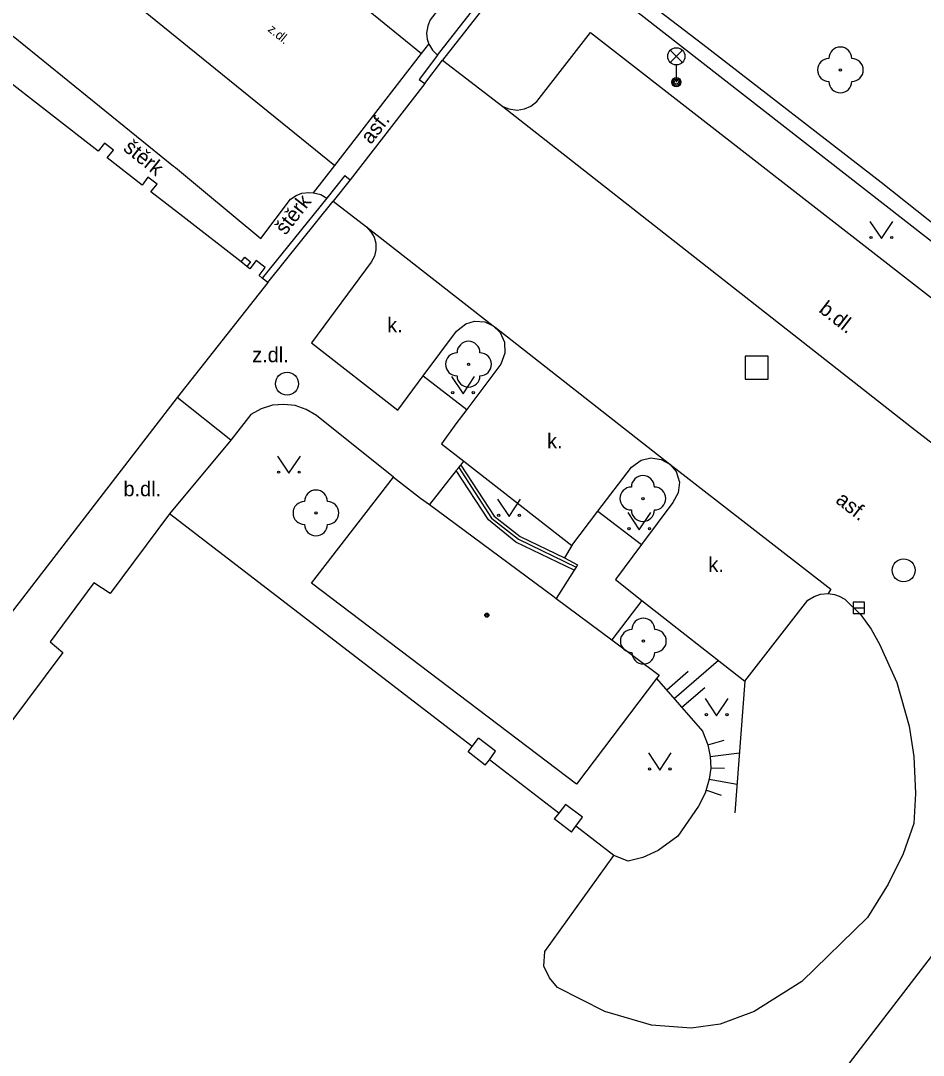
# Model space of a CAD drawing. Extents: x -598932 to -598196, y -1162207 to -1161504.
# Drawn here: x -598730.26 to -598690.86, y -1162044.52 to -1161999.37 of the extents above; entities that cross this region are included whole.
import ezdxf

# ---------------------------------------------------------------- set-up
doc = ezdxf.new("R2010")
doc.units = 0
for name, color, linetype in [('Level 22', 7, 'Continuous'), ('Level 26', 7, 'Continuous'), ('Level 27', 7, 'Continuous'), ('Level 33', 7, 'Continuous'), ('Level 36', 7, 'Continuous'), ('Level 39', 7, 'Continuous'), ('silnoproud - povrch.  znaky a  RIS  skut. velikost', 7, 'Continuous'), ('specificka linie pasportu komunikaci', 7, 'Continuous'), ('TM - budovy zdene_ betonove - VP', 7, 'Continuous'), ('TM - chodniky - VP', 7, 'Continuous'), ('TM - dolni hrana svahu', 7, 'Continuous'), ('TM - horni hrana svahu', 7, 'Continuous'), ('TM - komunikace - VP', 7, 'Continuous'), ('TM - letecke snimky - pomocna linie', 7, 'Continuous'), ('TM - plot zdeny_ ohradni zed - VP', 7, 'Continuous'), ('TM - podezdivka plotu - VP', 7, 'Continuous'), ('TM - popis povrchu', 7, 'Continuous'), ('TM - rozhrani mezi zpev. plochami mezi sebou - VP', 7, 'Continuous'), ('TM - rozhrani ploch obecne - VP', 7, 'Continuous'), ('TM - srafovani', 7, 'Continuous'), ('TM - vjezd na pozemek', 7, 'Continuous'), ('TM - zabradli - VP', 7, 'Continuous')]:
    doc.layers.add(name, color=color, linetype=linetype)

msp = doc.modelspace()

# ---------------------------------------------------------------- linework, layer by layer
at = {"layer": 'Level 22'}
for centre in [(-598694.48, -1162001.52), (-598710.71, -1162014.36), (-598703.1, -1162020.22), (-598717.37, -1162020.85), (-598703.08, -1162026.44)]:
    msp.add_circle(centre, 0.05, dxfattribs=at)
for centre, start, end in [((-598694.48, -1162001.02), 359.9626, 179.9626), ((-598694.98, -1162001.52), 89.9626, 269.9626), ((-598693.98, -1162001.52), 269.9626, 89.9626), ((-598694.48, -1162002.02), 179.9626, 359.9626), ((-598710.71, -1162013.86), 0, 180), ((-598711.21, -1162014.36), 90, 270), ((-598710.21, -1162014.36), 270, 90), ((-598710.71, -1162014.86), 180, 0), ((-598703.1, -1162019.72), 0, 180), ((-598717.37, -1162020.35), 0, 180), ((-598703.6, -1162020.22), 90, 270), ((-598702.6, -1162020.22), 270, 90), ((-598717.87, -1162020.85), 90, 270), ((-598716.87, -1162020.85), 270, 90), ((-598703.1, -1162020.72), 180, 0), ((-598717.37, -1162021.35), 180, 0), ((-598703.08, -1162025.94), 0, 180), ((-598703.58, -1162026.44), 90, 270), ((-598702.58, -1162026.44), 270, 90), ((-598703.08, -1162026.94), 180, 0)]:
    msp.add_arc(centre, 0.5, start, end, dxfattribs=at)
at = {"layer": 'Level 26'}
msp.add_lwpolyline([(-598698.63, -1162015.01), (-598697.63, -1162015.01), (-598697.63, -1162014.01), (-598698.63, -1162014.01)], close=True, dxfattribs=at)
at = {"layer": 'Level 27'}
msp.add_line((-598693.92, -1162024.99), (-598693.42, -1162024.99), dxfattribs=at)
msp.add_lwpolyline([(-598693.92, -1162025.24), (-598693.42, -1162025.24), (-598693.42, -1162024.74), (-598693.92, -1162024.74)], close=True, dxfattribs=at)
for centre in [(-598718.63, -1162015.21), (-598691.72, -1162023.35)]:
    msp.add_circle(centre, 0.5, dxfattribs=at)
at = {"layer": 'Level 33'}
for p, q in [((-598701.905, -1162001.19), (-598701.375, -1162000.66)), ((-598701.905, -1162000.66), (-598701.375, -1162001.19)), ((-598701.64, -1162001.3), (-598701.64, -1162002.05))]:
    msp.add_line(p, q, dxfattribs=at)
for centre, radius in [((-598701.64, -1162000.925), 0.375), ((-598701.64, -1162002.05), 0.2), ((-598701.64, -1162002.05), 0.145), ((-598701.64, -1162002.05), 0.0876)]:
    msp.add_circle(centre, radius, dxfattribs=at)
at = {"layer": 'Level 36'}
for points in [[(-598693.19, -1162008.13), (-598692.69, -1162008.88), (-598692.19, -1162008.13)], [(-598711.45, -1162014.9), (-598710.95, -1162015.65), (-598710.45, -1162014.9)], [(-598719.05, -1162018.37), (-598718.55, -1162019.12), (-598718.05, -1162018.37)], [(-598709.44, -1162020.25), (-598708.94, -1162021), (-598708.44, -1162020.25)], [(-598703.76, -1162020.83), (-598703.26, -1162021.58), (-598702.76, -1162020.83)], [(-598700.38, -1162028.95), (-598699.88, -1162029.7), (-598699.38, -1162028.95)], [(-598702.86, -1162031.32), (-598702.36, -1162032.07), (-598701.86, -1162031.32)]]:
    msp.add_lwpolyline(points, dxfattribs=at)
for centre in [(-598693.14, -1162008.83), (-598692.241, -1162008.83), (-598711.4, -1162015.6), (-598710.501, -1162015.6), (-598719, -1162019.07), (-598718.101, -1162019.07), (-598709.39, -1162020.95), (-598708.491, -1162020.95), (-598703.71, -1162021.53), (-598702.811, -1162021.53), (-598700.33, -1162029.65), (-598699.431, -1162029.65), (-598702.81, -1162032.02), (-598701.911, -1162032.02)]:
    msp.add_circle(centre, 0.05, dxfattribs=at)
at = {"layer": 'Level 39'}
for radius in [0.09, 0.0398]:
    msp.add_circle((-598709.91, -1162025.31), radius, dxfattribs=at)
at = {"layer": 'silnoproud - povrch.  znaky a  RIS  skut. velikost'}
for points in [[(-598720.64, -1162009.89), (-598720.48, -1162009.69)], [(-598720.48, -1162009.69), (-598720.23, -1162009.89)], [(-598720.23, -1162009.89), (-598720.38, -1162010.09)]]:
    msp.add_lwpolyline(points, dxfattribs=at)
at = {"layer": 'specificka linie pasportu komunikaci'}
for points in [[(-598738.52, -1161979.88), (-598712.76, -1162000.8)], [(-598730.942, -1161994.014), (-598716.55, -1162005.69)]]:
    msp.add_lwpolyline(points, dxfattribs=at)
at = {"layer": 'TM - budovy zdene_ betonove - VP'}
for points in [[(-598726.6, -1162004.71), (-598726.87, -1162005.06), (-598731.22, -1162001.69), (-598730.94, -1162001.33)], [(-598726.21, -1162005.02), (-598726.6, -1162004.71)], [(-598724.7, -1162006.19), (-598724.96, -1162006.54), (-598726.48, -1162005.36), (-598726.21, -1162005.02)], [(-598724.3, -1162006.5), (-598724.7, -1162006.19)], [(-598719.98, -1162009.84), (-598720.25, -1162010.19), (-598720.38, -1162010.09), (-598720.64, -1162009.89), (-598723.18, -1162007.92), (-598724.57, -1162006.84), (-598724.3, -1162006.5)], [(-598719.58, -1162010.14), (-598719.98, -1162009.84)], [(-598719.47, -1162010.79), (-598719.71, -1162010.6), (-598719.85, -1162010.49), (-598719.58, -1162010.14)], [(-598719.47, -1162010.79), (-598723.42, -1162015.81)], [(-598723.42, -1162015.81), (-598741.79, -1162039.6)], [(-598717.56, -1162023.91), (-598713.99, -1162019.29)], [(-598713.99, -1162019.29), (-598712.8, -1162020.2)], [(-598712.8, -1162020.2), (-598712.42, -1162020.48)], [(-598712.42, -1162020.48), (-598707.03, -1162024.46)], [(-598705.99, -1162032.69), (-598717.56, -1162023.91)], [(-598707.03, -1162024.46), (-598706.88, -1162024.58)], [(-598706.88, -1162024.58), (-598704.46, -1162026.38)], [(-598704.46, -1162026.38), (-598702.39, -1162027.93)], [(-598702.5, -1162028.07), (-598705.99, -1162032.69)], [(-598702.39, -1162027.93), (-598702.5, -1162028.07)]]:
    msp.add_lwpolyline(points, dxfattribs=at)
at = {"layer": 'TM - chodniky - VP'}
for points in [[(-598712.69, -1162014.87), (-598710.78, -1162016.33)], [(-598713.99, -1162019.29), (-598717.34, -1162016.6), (-598717.79, -1162016.33), (-598718.28, -1162016.16), (-598718.77, -1162016.12), (-598719.27, -1162016.15), (-598719.76, -1162016.31), (-598720.21, -1162016.56), (-598721.08, -1162017.68)], [(-598721.08, -1162017.68), (-598723.76, -1162020.89)], [(-598711.05, -1162018.76), (-598710.92, -1162018.59)], [(-598711.25, -1162019), (-598711.14, -1162018.87)], [(-598709.84, -1162021.15), (-598711.25, -1162019)], [(-598711.14, -1162018.87), (-598711.05, -1162018.76)], [(-598705.07, -1162020.77), (-598703.16, -1162022.23)], [(-598708.65, -1162022.12), (-598709.84, -1162021.15)], [(-598706.1, -1162023.35), (-598708.65, -1162022.12)], [(-598706.2, -1162022.27), (-598706.52, -1162022.81)], [(-598706.52, -1162022.81), (-598705.95, -1162023.11)], [(-598705.95, -1162023.11), (-598706.01, -1162023.21)], [(-598706.01, -1162023.21), (-598706.1, -1162023.35)], [(-598703.14, -1162024.67), (-598704.46, -1162026.38)]]:
    msp.add_lwpolyline(points, dxfattribs=at)
at = {"layer": 'TM - dolni hrana svahu'}
msp.add_lwpolyline([(-598698.65, -1162028.19), (-598699.09, -1162033.93)], dxfattribs=at)
at = {"layer": 'TM - horni hrana svahu'}
msp.add_lwpolyline([(-598702.5, -1162028.07), (-598700.5, -1162030.37), (-598700.26, -1162030.97), (-598700.17, -1162031.47), (-598700.14, -1162031.99), (-598700.2, -1162032.46), (-598700.38, -1162033.07), (-598700.67, -1162033.64)], dxfattribs=at)
at = {"layer": 'TM - komunikace - VP'}
for points in [[(-598710.75, -1161997.22), (-598712.39, -1161999.33), (-598712.49, -1161999.59), (-598712.54, -1161999.91), (-598712.51, -1162000.18), (-598712.44, -1162000.39), (-598712.42, -1162000.44), (-598712.28, -1162000.66), (-598712.06, -1162000.88)], [(-598730.58, -1162000.05), (-598723.58, -1162005.71), (-598723.5, -1162005.78), (-598722.282, -1162006.792), (-598719.78, -1162008.87), (-598718.48, -1162007.16), (-598718.23, -1162006.99), (-598717.99, -1162006.9), (-598717.68, -1162006.86), (-598717.48, -1162006.88)], [(-598709.21, -1162003.11), (-598708.95, -1162003.22), (-598708.59, -1162003.27), (-598708.27, -1162003.22), (-598707.99, -1162003.1), (-598707.73, -1162002.9), (-598705.38, -1161999.88), (-598689.72, -1162012.07), (-598681.05, -1162018.84), (-598679.21, -1162017.8)], [(-598711.85, -1162001.09), (-598709.21, -1162003.11)], [(-598717.48, -1162006.88), (-598717.16, -1162006.96), (-598716.9, -1162007.11)], [(-598716.62, -1162007.24), (-598715.16, -1162008.37)], [(-598715.16, -1162008.37), (-598714.97, -1162008.58), (-598714.83, -1162008.81), (-598714.76, -1162009.08), (-598714.76, -1162009.37), (-598714.82, -1162009.64), (-598714.96, -1162009.91), (-598717.56, -1162013.42), (-598713.79, -1162016.36), (-598712.69, -1162014.87)], [(-598712.69, -1162014.87), (-598711.23, -1162012.91), (-598710.83, -1162012.59), (-598710.45, -1162012.48), (-598710, -1162012.51), (-598709.64, -1162012.68)], [(-598709.64, -1162012.68), (-598709.33, -1162012.97), (-598709.14, -1162013.39), (-598709.12, -1162013.87), (-598709.3, -1162014.35), (-598710.78, -1162016.33)], [(-598710.78, -1162016.33), (-598711.26, -1162016.96), (-598711.89, -1162017.84), (-598710.92, -1162018.59)], [(-598710.92, -1162018.59), (-598706.2, -1162022.27)], [(-598705.07, -1162020.77), (-598703.59, -1162018.85), (-598703.18, -1162018.54), (-598702.75, -1162018.44), (-598702.3, -1162018.51), (-598701.92, -1162018.72)], [(-598701.92, -1162018.72), (-598701.65, -1162019.04), (-598701.5, -1162019.5), (-598701.56, -1162019.97), (-598701.79, -1162020.39), (-598703.16, -1162022.23)], [(-598706.2, -1162022.27), (-598705.07, -1162020.77)], [(-598703.16, -1162022.23), (-598704.29, -1162023.75), (-598703.14, -1162024.67)], [(-598698.65, -1162028.19), (-598695.9, -1162024.66), (-598695.62, -1162024.49), (-598695.35, -1162024.39), (-598695.01, -1162024.36)], [(-598695.01, -1162024.36), (-598694.73, -1162024.41), (-598694.53, -1162024.48), (-598694.29, -1162024.61), (-598693.58, -1162025.3), (-598693.14, -1162025.92), (-598692.77, -1162026.58), (-598692.02, -1162028.25), (-598691.48, -1162030.16), (-598691.28, -1162031.47), (-598691.2, -1162033.09), (-598691.28, -1162034.4), (-598691.74, -1162035.73), (-598692.39, -1162037.04), (-598693.3, -1162038.5)], [(-598703.14, -1162024.67), (-598698.65, -1162028.19)]]:
    msp.add_lwpolyline(points, dxfattribs=at)
at = {"layer": 'TM - letecke snimky - pomocna linie'}
for points in [[(-598723.76, -1162020.89), (-598726.35, -1162024.36), (-598727.06, -1162023.9), (-598728.97, -1162026.48), (-598728.42, -1162026.94), (-598739.32, -1162041.51)], [(-598710.55, -1162031.04), (-598723.76, -1162020.89)], [(-598706.77, -1162033.95), (-598709.8, -1162031.62)], [(-598700.67, -1162033.64), (-598701.58, -1162034.95), (-598702.43, -1162035.58), (-598703.1, -1162035.88), (-598703.74, -1162036.05), (-598704.37, -1162035.79)], [(-598693.3, -1162038.5), (-598696.16, -1162041.3), (-598698.24, -1162042.61), (-598699.72, -1162043.16), (-598700.99, -1162043.33), (-598702.72, -1162043.2), (-598704.76, -1162042.61), (-598706.83, -1162041.55), (-598707.17, -1162041.13), (-598707.42, -1162040.62), (-598707.38, -1162039.98), (-598704.37, -1162035.79), (-598706.02, -1162034.52)], [(-598690.52, -1162040.21), (-598731.51, -1162093.49), (-598727.7, -1162096.43)]]:
    msp.add_lwpolyline(points, dxfattribs=at)
at = {"layer": 'TM - plot zdeny_ ohradni zed - VP'}
for points in [[(-598707.52, -1161995.01), (-598707.25, -1161995.22), (-598700.48, -1162000.4)], [(-598712.06, -1162000.88), (-598709.8, -1161997.96)], [(-598700.48, -1162000.4), (-598692.7, -1162006.41), (-598684.92, -1162012.59)], [(-598712.06, -1162000.88), (-598712.87, -1162001.93)], [(-598716.11, -1162006.12), (-598716.9, -1162007.11), (-598719.71, -1162010.6)]]:
    msp.add_lwpolyline(points, dxfattribs=at)
at = {"layer": 'TM - podezdivka plotu - VP'}
for points in [[(-598707.25, -1161995.22), (-598707.6, -1161995.67), (-598711.85, -1162001.09)], [(-598679.21, -1162017.8), (-598707.6, -1161995.67)], [(-598712.62, -1162002.11), (-598711.85, -1162001.09)], [(-598712.87, -1162001.93), (-598712.62, -1162002.11)], [(-598716.11, -1162006.12), (-598715.88, -1162006.32), (-598716.62, -1162007.24)], [(-598719.47, -1162010.79), (-598716.62, -1162007.24)]]:
    msp.add_lwpolyline(points, dxfattribs=at)
at = {"layer": 'TM - rozhrani mezi zpev. plochami mezi sebou - VP'}
msp.add_lwpolyline([(-598717.48, -1162006.88), (-598716.55, -1162005.69), (-598712.76, -1162000.8), (-598712.44, -1162000.39)], dxfattribs=at)
at = {"layer": 'TM - rozhrani ploch obecne - VP'}
for points in [[(-598709.21, -1162003.11), (-598691.37, -1162017.11), (-598677.61, -1162027.74)], [(-598715.16, -1162008.37), (-598709.64, -1162012.68)], [(-598709.64, -1162012.68), (-598709.55, -1162012.74)], [(-598709.55, -1162012.74), (-598701.92, -1162018.72)], [(-598721.08, -1162017.68), (-598723.42, -1162015.81)], [(-598711.25, -1162019), (-598712.42, -1162020.48)], [(-598711.05, -1162018.76), (-598709.59, -1162020.99), (-598708.46, -1162021.88), (-598706.52, -1162022.81)], [(-598701.92, -1162018.72), (-598694.89, -1162024.17), (-598695.01, -1162024.36)], [(-598706.1, -1162023.35), (-598706.88, -1162024.58)], [(-598710.73, -1162031.28), (-598710.55, -1162031.04), (-598710.28, -1162030.67)], [(-598709.53, -1162031.25), (-598710.28, -1162030.67)], [(-598709.98, -1162031.86), (-598710.73, -1162031.28)], [(-598709.98, -1162031.86), (-598709.8, -1162031.62), (-598709.53, -1162031.25)], [(-598706.48, -1162033.57), (-598706.77, -1162033.95), (-598706.97, -1162034.2)], [(-598705.73, -1162034.12), (-598706.48, -1162033.57)], [(-598706.21, -1162034.78), (-598706.97, -1162034.2)], [(-598706.21, -1162034.78), (-598706.02, -1162034.52), (-598705.73, -1162034.12)]]:
    msp.add_lwpolyline(points, dxfattribs=at)
at = {"layer": 'TM - srafovani'}
for points in [[(-598699.8, -1162027.29), (-598701.73, -1162028.96)], [(-598701.13, -1162027.77), (-598702.05, -1162028.58)], [(-598701.4, -1162029.33), (-598700.4, -1162028.47)], [(-598700.26, -1162030.97), (-598699.55, -1162030.77)], [(-598700.17, -1162031.47), (-598698.89, -1162031.31)], [(-598700.15, -1162031.97), (-598699.54, -1162031.99)], [(-598700.2, -1162032.46), (-598698.99, -1162032.68)], [(-598700.33, -1162032.94), (-598699.69, -1162033.17)]]:
    msp.add_lwpolyline(points, dxfattribs=at)
at = {"layer": 'TM - vjezd na pozemek'}
msp.add_lwpolyline([(-598712.62, -1162002.11), (-598715.88, -1162006.32)], dxfattribs=at)
at = {"layer": 'TM - zabradli - VP'}
msp.add_lwpolyline([(-598711.14, -1162018.87), (-598709.7, -1162021.08), (-598708.53, -1162021.99), (-598706.01, -1162023.21)], dxfattribs=at)

# ---------------------------------------------------------------- texts
at = {"layer": 'TM - popis povrchu'}
for s, height, rotation, p in [('z.dl.', 0.4, 320.9114, (-598719.5, -1161999.8)), ('asf.', 0.65, 52, (-598714.97, -1162004.8)), ('štěrk', 0.65, 321.3652, (-598725.82, -1162005)), ('štěrk', 0.65, 52.0263, (-598718.7, -1162008.76)), ('b.dl.', 0.65, 322, (-598695.46, -1162012.05)), ('asf.', 0.65, 322, (-598694.73, -1162020.37))]:
    msp.add_text(s, height=height, rotation=rotation, dxfattribs=at).set_placement(p)
for s, p in [('k.', (-598714.26, -1162012.97)), ('z.dl.', (-598720.15, -1162014.27)), ('k.', (-598707.28, -1162018.03)), ('b.dl.', (-598725.77, -1162020.12)), ('k.', (-598700.24, -1162023.42))]:
    msp.add_text(s, height=0.65, dxfattribs=at).set_placement(p)

doc.saveas('drawing.dxf')
